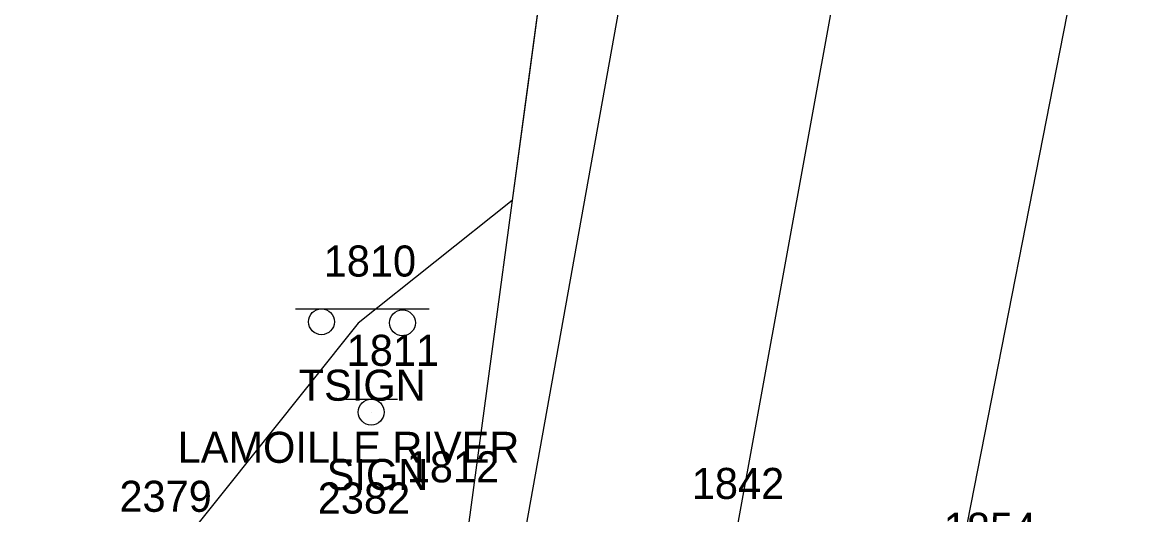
# Model space of a CAD drawing. Extents: x 1472022 to 1479249, y 777216 to 786527.
# Drawn here: x 1473622.4 to 1473693.9, y 779853.1 to 779884.8 of the extents above; entities that cross this region are included whole.
import ezdxf

# ---------------------------------------------------------------- set-up
doc = ezdxf.new("R2010")
doc.units = 0
for name, color, linetype in [('L_I', 7, 'Continuous'), ('LSOGP', 7, 'Continuous'), ('P_I', 7, 'Continuous'), ('PET', 7, 'Continuous'), ('PRC', 7, 'Continuous'), ('PSP', 7, 'Continuous'), ('S_A', 7, 'Continuous'), ('S_C', 7, 'Continuous'), ('S_I', 7, 'Continuous'), ('SSGN', 7, 'Continuous')]:
    doc.layers.add(name, color=color, linetype=linetype)

msp = doc.modelspace()

# ---------------------------------------------------------------- linework, layer by layer
at = {"layer": 'LSOGP'}
msp.add_lwpolyline([(1473656.072, 779888.846), (1473655.033, 779881.108), (1473653.993, 779873.371), (1473644.063, 779865.462), (1473631.968, 779850.307), (1473599.661, 779855.69), (1473579.919, 779858.134), (1473556.927, 779858.568), (1473561.404, 779839.673), (1473563.025, 779816.952), (1473553.61, 779800.93), (1473556.198, 779785.034)], dxfattribs=at)
at = {"layer": 'PET'}
for points in [[(1473794.134, 780615.244), (1473782.523, 780552.374), (1473771.203, 780492.116), (1473760.187, 780429.945), (1473749.17, 780369.329), (1473737.054, 780303.749), (1473725.278, 780241.428), (1473714.846, 780182.671), (1473704.328, 780127.346), (1473693.075, 780062.48), (1473683.101, 780008.622), (1473673.009, 779953.253), (1473663.963, 779903.08), (1473652.834, 779841.006), (1473649.095, 779822.998)], [(1473823.421, 780612.386), (1473811.332, 780545.889), (1473800.437, 780487.514), (1473789.09, 780424.894), (1473785.107, 780403.281), (1473778.081, 780362.228), (1473770.888, 780328.953), (1473766.974, 780298.796), (1473754.948, 780235.541), (1473743.531, 780174.64), (1473733.794, 780120.941), (1473722.51, 780060.445), (1473711.988, 780003.091), (1473701.805, 779948.067), (1473692.047, 779897.361), (1473680.213, 779836.904), (1473679.287, 779834.871), (1473676.239, 779818.177), (1473663.538, 779820.453), (1473649.095, 779822.998)]]:
    msp.add_lwpolyline(points, dxfattribs=at)
at = {"layer": 'PRC'}
msp.add_lwpolyline([(1473807.59, 780614.569), (1473795.532, 780548.627), (1473784.81, 780489.966), (1473773.424, 780426.813), (1473762.255, 780366.775), (1473750.55, 780303.147), (1473738.693, 780240.187), (1473727.911, 780180.806), (1473717.594, 780123.603), (1473707.015, 780064.191), (1473696.415, 780006.238), (1473686.637, 779951.223), (1473677.198, 779900.335), (1473668.242, 779851.135), (1473663.538, 779820.453)], dxfattribs=at)
at = {"layer": 'PSP'}
msp.add_lwpolyline([(1473785.489, 780617.448), (1473774.094, 780553.904), (1473763.032, 780493.848), (1473751.836, 780432.119), (1473740.578, 780370.871), (1473727.951, 780303.666), (1473717.241, 780242.769), (1473706.307, 780183.736), (1473696.114, 780128.972), (1473684.008, 780064.224), (1473674.482, 780009.553), (1473665.573, 779955.553), (1473658.152, 779904.321), (1473649.833, 779842.421), (1473649.998, 779841.098), (1473646.898, 779823.468)], dxfattribs=at)
at = {"layer": 'SSGN'}
for p, q in [((1473640.047, 779866.383), (1473648.644, 779866.383)), ((1473644.069, 779865.479), (1473644.069, 779865.479)), ((1473643.262, 779860.563), (1473646.595, 779860.563)), ((1473644.909, 779859.73), (1473644.909, 779859.73))]:
    msp.add_line(p, q, dxfattribs=at)
for centre in [(1473641.708, 779865.55), (1473646.922, 779865.479), (1473644.909, 779859.73)]:
    msp.add_circle(centre, 0.833, dxfattribs=at)

# ---------------------------------------------------------------- texts
at = {"layer": 'L_I'}
for s, p in [('2379', (1473628.7, 779853.307)), ('2382', (1473641.469, 779853.195))]:
    msp.add_text(s, height=2, dxfattribs=at).set_placement(p)
at = {"layer": 'P_I'}
msp.add_text('1842', height=2, dxfattribs=at).set_placement((1473665.549, 779854.135))
at = {"layer": 'S_A'}
for s, p in [('TSIGN', (1473640.244, 779860.462)), ('SIGN', (1473642.046, 779854.71))]:
    msp.add_text(s, height=2, dxfattribs=at).set_placement(p)
at = {"layer": 'S_C'}
msp.add_text('LAMOILLE RIVER', height=2, dxfattribs=at).set_placement((1473632.449, 779856.462))
at = {"layer": 'S_I'}
for s, p in [('1810', (1473641.851, 779868.462)), ('1811', (1473643.33, 779862.71)), ('1812', (1473647.2, 779855.206)), ('1854', (1473681.769, 779851.247))]:
    msp.add_text(s, height=2, dxfattribs=at).set_placement(p)

doc.saveas('drawing.dxf')
